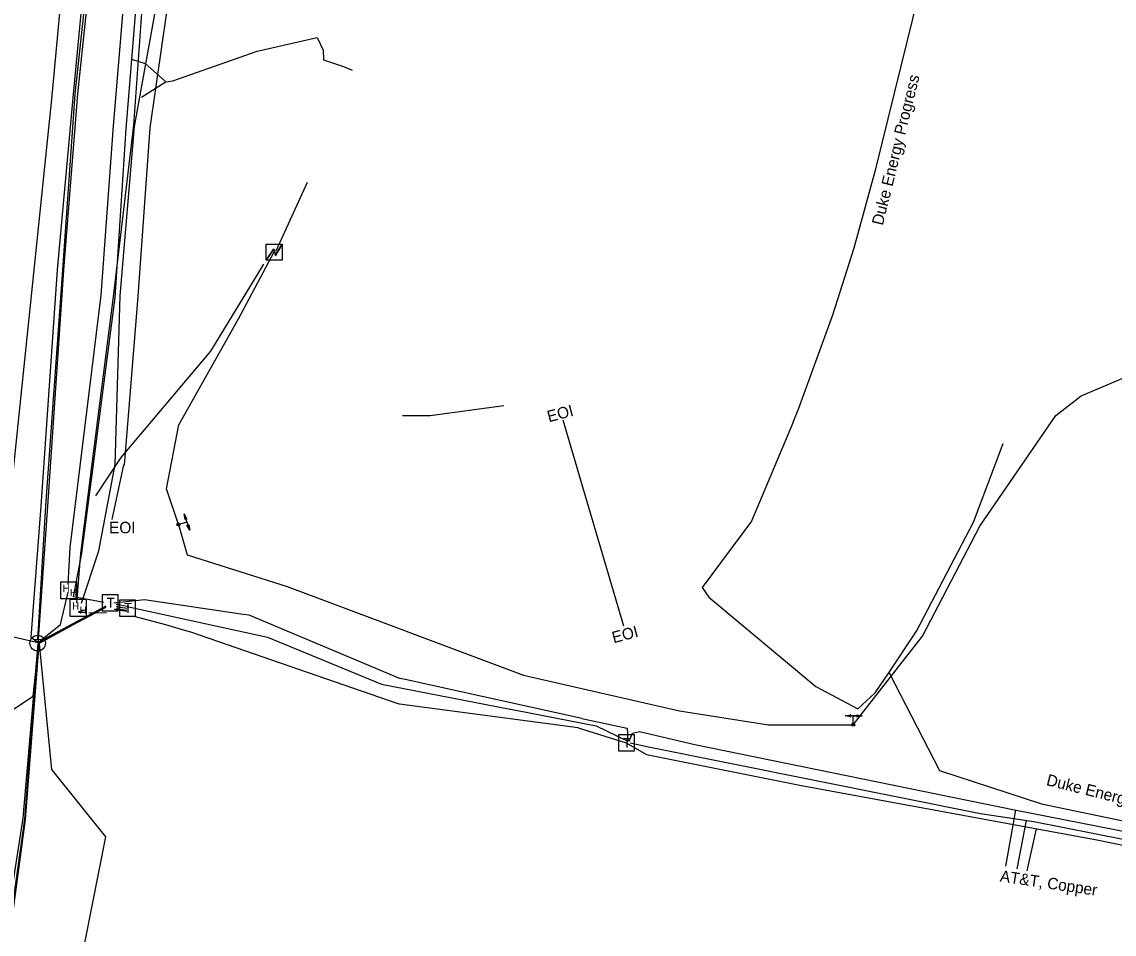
# Model space of a CAD drawing. Extents: x 2070721 to 2083039, y 729290 to 737883.
# Drawn here: x 2082364.3 to 2082745.3, y 736148.2 to 736466.5 of the extents above; entities that cross this region are included whole.
import ezdxf

# ---------------------------------------------------------------- set-up
doc = ezdxf.new("R2010")
doc.units = 0
for name, color, linetype in [('Exist Utilities Gas Valve Cogo Elevation', 7, 'Continuous'), ('Exist Utilities Power Pole CELL', 7, 'Continuous'), ('Exist Utilities Power Pole Cogo Elevation', 7, 'Continuous'), ('Exist Utilities Power UG Cable Cogo Point CELL', 7, 'Continuous'), ('Exist Utilities Power UG Cable SUE LOS B Cogo Point CELL', 7, 'Continuous'), ('Exist Utilities Telephone Hand Hole Cogo Number', 7, 'Continuous'), ('Exist Utilities Telephone UG Cable Cogo Point CELL', 7, 'Continuous'), ('Exist Utilities Telephone UG Cable SUE LOS C Cogo Comment', 7, 'Continuous'), ('Exist Utilities Telephone UG Cable SUE LOS C Cogo Number', 7, 'Continuous'), ('Exist Utilities Telephone UG Cable SUE LOS C Cogo Point CELL', 7, 'Continuous'), ('Exist Utilities Telephone UG FO SUE LOS B Cogo Comment', 7, 'Continuous'), ('Exist Utilities Telephone UG FO SUE LOS B Cogo Number', 7, 'Continuous'), ('Exist Utilities TV Pedestal CELL', 7, 'Continuous'), ('Exist Utilities TV Pedestal Cogo Elevation', 7, 'Continuous'), ('Exist Utilities TV UG Cable Cogo Point CELL', 7, 'Continuous'), ('Exist Utilities TV UG Cable SUE LOS C Cogo Comment', 7, 'Continuous'), ('Exist Utilities TV UG Cable SUE LOS C Cogo Point CELL', 7, 'Continuous'), ('Exist Utilities Water Meter CELL', 7, 'Continuous'), ('Exist Utilities Water Meter Cogo Number', 7, 'Continuous'), ('Exist Utilities Water UG Line SUE LOS B Cogo Number', 7, 'Continuous')]:
    doc.layers.add(name, color=color, linetype=linetype)

msp = doc.modelspace()

# ---------------------------------------------------------------- linework, layer by layer
at = {"layer": 'Exist Utilities Gas Valve Cogo Elevation'}
for p, q in [((2082710.95, 736191.5), (2082707.48, 736172)), ((2082714.68, 736187.84), (2082711.35, 736171)), ((2082718.1, 736185.01), (2082714.92, 736170.35))]:
    msp.add_line(p, q, dxfattribs=at)
at = {"layer": 'Exist Utilities Power Pole CELL'}
for points in [[(2082396.3, 736612.75), (2082392.62, 736561.83), (2082388.6, 736508.73), (2082382.17, 736441.21), (2082376.53, 736380.02), (2082370.92, 736297.49), (2082367.41, 736251.8), (2082369.98, 736249.96), (2082368.85, 736250.78)], [(2082370.04, 736251.07), (2082373.38, 736297.59), (2082378.96, 736379.81), (2082383.81, 736441.35), (2082390.88, 736508.81), (2082395.35, 736561.8), (2082398.47, 736612.36)], [(2082121.11, 735111.12), (2082125.96, 735163.62), (2082138.7, 735257.13), (2082145.62, 735320.66), (2082168.01, 735429.9), (2082199.18, 735564.38), (2082231.58, 735685.7), (2082254.18, 735727.05), (2082277.17, 735809.42), (2082316.95, 735921.54), (2082334, 735994.14), (2082349.07, 736088.38), (2082364.7, 736188.68), (2082369.94, 736249.54)], [(2082122.2, 735109.35), (2082127.71, 735163.64), (2082140.55, 735257.07), (2082148.23, 735320.74), (2082172.1, 735428.75), (2082203.63, 735562.9), (2082234.11, 735686.98), (2082254.24, 735726.85), (2082280.4, 735808.61), (2082320.45, 735920.23), (2082334.66, 735993.58), (2082351.98, 736087.59), (2082365.57, 736188.21), (2082370.28, 736249.44)], [(2082311, 735883.41), (2082314.93, 735894.57), (2082321.33, 735919.82), (2082336.09, 735960.51), (2082359.13, 735988.75), (2082348, 736007.91), (2082360.44, 736082.28), (2082381.79, 736122.83), (2082393.52, 736182.23), (2082374.75, 736205.67), (2082370.42, 736249.5)]]:
    msp.add_lwpolyline(points, dxfattribs=at)
at = {"layer": 'Exist Utilities Power Pole Cogo Elevation'}
for points in [[(2082418.9, 736291.15), (2082414.75, 736303.55), (2082418.98, 736325.85), (2082439.82, 736362.86), (2082452.35, 736386.28)], [(2082456.86, 736269.48), (2082539.23, 736238.57), (2082593.67, 736226.14), (2082624.7, 736221.3), (2082654.33, 736221.3)], [(2082666.83, 736239.42), (2082684.44, 736205.31), (2082720.04, 736193.67), (2082747.93, 736187.86), (2082781.39, 736180)]]:
    msp.add_lwpolyline(points, dxfattribs=at)
at = {"layer": 'Exist Utilities Power UG Cable Cogo Point CELL'}
for p, q in [((2082422.82, 736289.15), (2082420.93, 736294.81)), ((2082418.9, 736291.15), (2082421.83, 736292.12)), ((2082418.9, 736291.15), (2082418.9, 736291.15)), ((2082421.83, 736292.12), (2082422.82, 736289.15)), ((2082657.47, 736224.38), (2082651.5, 736224.38)), ((2082654.33, 736221.3), (2082654.33, 736224.38)), ((2082654.33, 736224.38), (2082657.47, 736224.38)), ((2082654.33, 736221.3), (2082654.33, 736221.3))]:
    msp.add_line(p, q, dxfattribs=at)
for points in [[(2082420.93, 736294.81), (2082421.88, 736293.05), (2082421.42, 736293.33), (2082421.25, 736292.88)], [(2082422.82, 736289.15), (2082421.87, 736290.91), (2082422.33, 736290.62), (2082422.5, 736291.08)], [(2082651.5, 736224.38), (2082653.47, 736224.73), (2082653.05, 736224.38), (2082653.44, 736224.08)], [(2082657.47, 736224.38), (2082655.49, 736224.04), (2082655.91, 736224.38), (2082655.53, 736224.69)]]:
    msp.add_lwpolyline(points, close=True, dxfattribs=at)
for centre in [(2082418.9, 736291.15), (2082654.33, 736221.3)]:
    msp.add_circle(centre, 0.517, dxfattribs=at)
at = {"layer": 'Exist Utilities Telephone UG Cable Cogo Point CELL'}
msp.add_line((2082383.94, 736262.09), (2082383.94, 736262.09), dxfattribs=at)
msp.add_lwpolyline([(2082381.06, 736259.21), (2082386.81, 736259.21), (2082386.81, 736264.96), (2082381.06, 736264.96), (2082381.06, 736259.21)], dxfattribs=at)
at = {"layer": 'Exist Utilities Telephone UG Cable SUE LOS C Cogo Comment'}
for points in [[(2082395.72, 736292.86), (2082399.83, 736311.96), (2082400.03, 736311.89), (2082404.85, 736370.66), (2082409.06, 736429.49), (2082414.93, 736470.65), (2082419.29, 736514.19), (2082420.3, 736517.77)], [(2082574.24, 736255.68), (2082559.38, 736306.12), (2082553.11, 736327.59)], [(2082418.9, 736291.15), (2082421.9, 736280.56), (2082456.86, 736269.48)]]:
    msp.add_lwpolyline(points, dxfattribs=at)
at = {"layer": 'Exist Utilities Telephone UG Cable SUE LOS C Cogo Number'}
msp.add_line((2082452.35, 736386.28), (2082452.35, 736386.28), dxfattribs=at)
msp.add_lwpolyline([(2082449.51, 736388.89), (2082455.06, 736388.89), (2082455.06, 736383.34), (2082449.51, 736383.34)], close=True, dxfattribs=at)
for points in [[(2082449.51, 736383.34), (2082452.15, 736387.28), (2082452.78, 736385.07), (2082455.06, 736388.89)], [(2082449.58, 736383.34), (2082452.15, 736387.07), (2082452.74, 736384.89), (2082455.06, 736388.74)]]:
    msp.add_lwpolyline(points, dxfattribs=at)
at = {"layer": 'Exist Utilities Telephone UG Cable SUE LOS C Cogo Point CELL'}
msp.add_circle((2082369.79, 736249.74), 2.72, dxfattribs=at)
at = {"layer": 'Exist Utilities Telephone UG FO SUE LOS B Cogo Comment'}
for p, q in [((2082395.01, 736263.86), (2082395.01, 736263.86)), ((2082401.04, 736262.02), (2082401.04, 736262.02)), ((2082575.12, 736215.01), (2082575.12, 736215.01))]:
    msp.add_line(p, q, dxfattribs=at)
for points in [[(2082392.29, 736261.03), (2082397.88, 736261.03), (2082397.88, 736266.63), (2082392.29, 736266.63), (2082392.29, 736261.03)], [(2082398.32, 736259.19), (2082403.91, 736259.19), (2082403.91, 736264.79), (2082398.32, 736264.79), (2082398.32, 736259.19)], [(2082572.4, 736212.18), (2082577.99, 736212.18), (2082577.99, 736217.77), (2082572.4, 736217.77), (2082572.4, 736212.18)]]:
    msp.add_lwpolyline(points, dxfattribs=at)
at = {"layer": 'Exist Utilities Telephone UG FO SUE LOS B Cogo Number'}
for p, q in [((2082377.71, 736271.07), (2082377.71, 736265.35)), ((2082383.43, 736271.07), (2082377.71, 736271.07)), ((2082383.43, 736265.35), (2082383.43, 736271.07)), ((2082380.57, 736268.21), (2082380.57, 736268.21)), ((2082377.71, 736265.35), (2082383.43, 736265.35))]:
    msp.add_line(p, q, dxfattribs=at)
at = {"layer": 'Exist Utilities TV Pedestal CELL'}
for p, q in [((2082384.01, 736260.54), (2082386.35, 736260.56)), ((2082384.14, 736260.82), (2082386.4, 736261.38))]:
    msp.add_line(p, q, dxfattribs=at)
for points in [[(2082383.39, 736263.77), (2082384.87, 736281.05), (2082388.71, 736311.38), (2082396.25, 736370.54), (2082403.33, 736430.4), (2082406.33, 736472.77), (2082407.72, 736494.25), (2082413.13, 736522.51), (2082423.07, 736531.36)], [(2082385.03, 736263.7), (2082391.12, 736281.95), (2082396.82, 736312.11), (2082398.55, 736370.94), (2082403.55, 736430), (2082411.08, 736471.72), (2082411.73, 736494.17), (2082412, 736522.79), (2082423.09, 736530.34)]]:
    msp.add_lwpolyline(points, dxfattribs=at)
at = {"layer": 'Exist Utilities TV Pedestal Cogo Elevation'}
msp.add_lwpolyline([(2082359.3, 736290.13), (2082359.45, 736292.32), (2082374.67, 736439.46), (2082381.09, 736508.57), (2082384.35, 736558.86)], dxfattribs=at)
at = {"layer": 'Exist Utilities TV UG Cable Cogo Point CELL'}
for p, q in [((2082393.52, 736262.7), (2082370.29, 736250.16)), ((2082397.16, 736262.53), (2082400.95, 736262.01)), ((2082401.02, 736262.58), (2082397.18, 736263.21)), ((2082393.34, 736262.2), (2082369.98, 736249.96)), ((2082393.55, 736262.24), (2082370.29, 736249.87)), ((2082400.87, 736260.81), (2082396.53, 736261.53)), ((2082400.91, 736261.12), (2082397.03, 736261.67)), ((2082558.33, 736220.24), (2082575.15, 736215.01))]:
    msp.add_line(p, q, dxfattribs=at)
for points in [[(2082392.88, 736263.89), (2082382.27, 736265.88), (2082385.19, 736281.09), (2082389.11, 736311.29), (2082396.78, 736370.29), (2082400.63, 736429.15), (2082404.26, 736473.32), (2082405.87, 736494.42), (2082409.26, 736525.23), (2082412.82, 736576.27), (2082417.8, 736608.3), (2082461.47, 736609.04), (2082528.72, 736605.28), (2082588.4, 736613.3), (2082637.77, 736629.11), (2082670.84, 736641.95), (2082696.51, 736666.16)], [(2082396.41, 736263.85), (2082407.06, 736264.95), (2082441.51, 736259.83)], [(2082401.02, 736262.58), (2082450.02, 736251.87), (2082489.79, 736235.41), (2082534.59, 736226.68), (2082536.66, 736226.37), (2082564.69, 736220.9), (2082575.67, 736215.61)], [(2082309.03, 736200.13), (2082349.47, 736218.89), (2082368.17, 736231.22), (2082370.24, 736249.61), (2082392.9, 736262.1)], [(2082403.39, 736259.13), (2082414.33, 736256.27), (2082421.34, 736254.2)], [(2082441.51, 736259.83), (2082443.48, 736259.57), (2082496.24, 736237.42)], [(2082421.34, 736254.2), (2082423.13, 736253.74), (2082495.39, 736228.71)], [(2082559.58, 736223.51), (2082498, 736237.05), (2082496.24, 736237.42)], [(2082558.33, 736220.24), (2082496.03, 736228.51), (2082495.39, 736228.71)], [(2082559.58, 736223.51), (2082575.46, 736220.04), (2082575.67, 736215.61)], [(2082576.13, 736215.54), (2082577.26, 736218.31), (2082579.78, 736218.88)], [(2082579.78, 736218.88), (2082599.02, 736214.41), (2082710.61, 736191.57), (2082798.37, 736174.45), (2082885.43, 736159.26), (2082946, 736165.14)], [(2082575.12, 736215.01), (2082582.19, 736210.9), (2082636.27, 736200.06), (2082738.67, 736181.25), (2082876.05, 736153.29), (2082889.8, 736152.19), (2082917.84, 736153.8), (2082948.81, 736158.4)], [(2082576.46, 736214.97), (2082582.9, 736213.6), (2082698.76, 736190.27)], [(2082698.76, 736190.27), (2082717.32, 736187.56), (2082780.79, 736175), (2082844.8, 736163.86), (2082884.06, 736155.9), (2082910.3, 736157.05), (2082932.08, 736160.96), (2082946.85, 736162.6)]]:
    msp.add_lwpolyline(points, dxfattribs=at)
at = {"layer": 'Exist Utilities TV UG Cable SUE LOS C Cogo Comment'}
for p, q in [((2082463.81, 736410.44), (2082452.84, 736386.5)), ((2082387.6, 736260.34), (2082393.82, 736260.4))]:
    msp.add_line(p, q, dxfattribs=at)
for points in [[(2082633.41, 736326.82), (2082635.39, 736331.76), (2082647.25, 736364.29), (2082654.64, 736387.64), (2082662.17, 736415.15), (2082677.46, 736477.1), (2082686.22, 736495.26), (2082698.83, 736517.21), (2082712.08, 736532.18), (2082721.96, 736540.93)], [(2082414.59, 736445.57), (2082416.98, 736445.94), (2082446.41, 736456.23), (2082467.28, 736460.97), (2082469.35, 736456.58), (2082469.49, 736453.23), (2082476.52, 736450.86), (2082479.53, 736449.61)], [(2082402.51, 736453.49), (2082407.28, 736451.91), (2082414.3, 736445.82), (2082414.59, 736445.57)], [(2082414.59, 736445.57), (2082405.99, 736440.03)], [(2082448.58, 736381.94), (2082430.13, 736351.6), (2082398.76, 736314.47), (2082389.97, 736301.15)], [(2082654.33, 736221.3), (2082678.51, 736252.19), (2082698.5, 736290.59), (2082725, 736329.21), (2082733.89, 736336.05), (2082785.68, 736358.04), (2082804, 736366.39)], [(2082532.37, 736332.5), (2082506.75, 736329), (2082497.01, 736329)], [(2082633.41, 736326.82), (2082618.79, 736292.34), (2082601.67, 736269.13), (2082603.94, 736265.79), (2082641.3, 736234.65), (2082655.87, 736226.86), (2082661.97, 736232.43), (2082666.77, 736239.35), (2082676.44, 736253.93), (2082696.29, 736292.01), (2082706.61, 736319.37)]]:
    msp.add_lwpolyline(points, dxfattribs=at)
at = {"layer": 'Exist Utilities TV UG Cable SUE LOS C Cogo Point CELL'}
for points in [[(2082369.85, 736250.96), (2082372.63, 736297.63), (2082378.59, 736379.94), (2082382.86, 736441.28), (2082390.24, 736508.9), (2082394.52, 736561.91), (2082398.1, 736612.48)], [(2082380.42, 736270.25), (2082381.12, 736283.15), (2082384.63, 736311.5), (2082391.98, 736371.16), (2082396.29, 736430.22), (2082399.86, 736473.26), (2082405.23, 736523.1), (2082417.88, 736536.05), (2082427.03, 736545.03), (2082447.47, 736546.52), (2082477.66, 736544.64), (2082535.53, 736545.32), (2082607.76, 736555.33), (2082628.77, 736564.28), (2082669.56, 736584.92)], [(2082370.7, 736250.6), (2082377.71, 736256.3), (2082380.43, 736267.48)], [(2082370.7, 736250.6), (2082377.71, 736256.3), (2082380.43, 736267.48)], [(2082120.86, 735106.65), (2082121.53, 735109.26), (2082126.82, 735163.37), (2082139.88, 735257.28), (2082147.13, 735321.1), (2082170.45, 735428.84), (2082201.87, 735563.79), (2082232.74, 735685.94), (2082254.12, 735726.65), (2082278.69, 735809.1), (2082319.03, 735920.81), (2082334.41, 735993.71), (2082351.13, 736088.05), (2082365.28, 736188.35), (2082370.12, 736249.49)]]:
    msp.add_lwpolyline(points, dxfattribs=at)
at = {"layer": 'Exist Utilities Water UG Line SUE LOS B Cogo Number'}
msp.add_line((2082297.68, 736266.81), (2082369.98, 736249.96), dxfattribs=at)

# ---------------------------------------------------------------- texts
at = {"layer": 'Exist Utilities Power UG Cable SUE LOS B Cogo Point CELL'}
for p in [(2082548.13, 736326.77), (2082570.74, 736249.69)]:
    msp.add_text('EOI', height=4, rotation=14.8382, dxfattribs=at).set_placement(p)
at = {"layer": 'Exist Utilities Telephone Hand Hole Cogo Number'}
msp.add_text('Duke Energy Progress', height=4, rotation=345.9467, dxfattribs=at).set_placement((2082721.44, 736200.28))
at = {"layer": 'Exist Utilities Telephone UG Cable Cogo Point CELL'}
for p in [(2082381.85, 736261.44), (2082384.43, 736259.98)]:
    msp.add_text('H', height=2.5, dxfattribs=at).set_placement(p)
at = {"layer": 'Exist Utilities Telephone UG Cable SUE LOS C Cogo Comment'}
msp.add_text('EOI', height=4, dxfattribs=at).set_placement((2082394.72, 736288.07))
at = {"layer": 'Exist Utilities Telephone UG Cable SUE LOS C Cogo Point CELL'}
msp.add_text('T', height=3.5, dxfattribs=at).set_placement((2082368.62, 736247.73))
at = {"layer": 'Exist Utilities Telephone UG FO SUE LOS B Cogo Comment'}
for p in [(2082393.88, 736262.15), (2082399.91, 736260.31), (2082573.99, 736213.29)]:
    msp.add_text('T', height=3.42, dxfattribs=at).set_placement(p)
at = {"layer": 'Exist Utilities Telephone UG FO SUE LOS B Cogo Number'}
for p in [(2082378.49, 736267.62), (2082381.06, 736266.15)]:
    msp.add_text('H', height=2.5, dxfattribs=at).set_placement(p)
at = {"layer": 'Exist Utilities Water Meter CELL'}
msp.add_text('Duke Energy Progress', height=4, rotation=76.1342, dxfattribs=at).set_placement((2082664.62, 736395.26))
at = {"layer": 'Exist Utilities Water Meter Cogo Number'}
msp.add_text('AT&T, Copper', height=4, rotation=351.5668, dxfattribs=at).set_placement((2082705.32, 736166.62))

doc.saveas('drawing.dxf')
